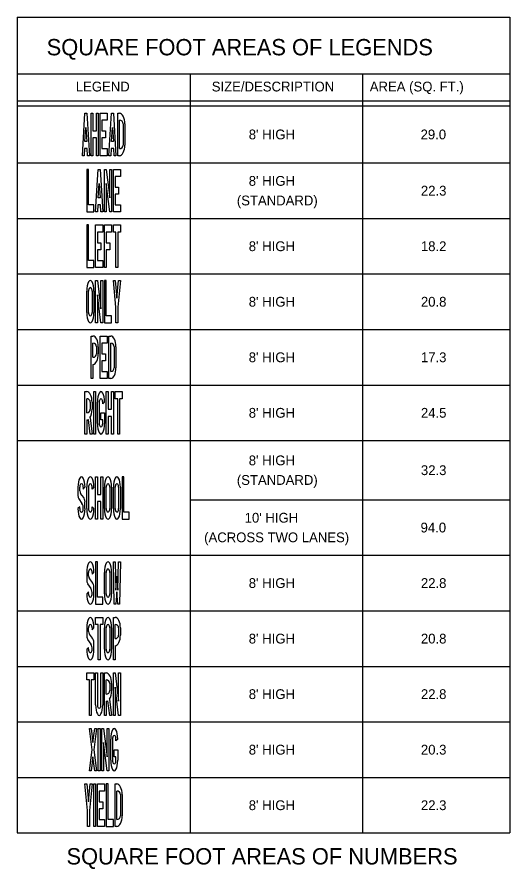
# Model space of a CAD drawing. Extents: x 9999.9 to 10007, y 10023.6 to 10033.8.
# Drawn here: x 10003.69 to 10006.71, y 10028.63 to 10033.85 of the extents above; entities that cross this region are included whole.
import ezdxf

# ---------------------------------------------------------------- set-up
doc = ezdxf.new("R2010")
doc.units = 0
doc.layers.add('DETL-LINE', color=7, linetype='Continuous')
doc.layers.add('DETL-NOTE', color=7, linetype='Continuous')

msp = doc.modelspace()

# ---------------------------------------------------------------- linework, layer by layer
at = {"layer": 'DETL-LINE'}
for points in [[(10004.1029, 10032.9967), (10004.0921, 10032.9967), (10004.1083, 10033.2568), (10004.1192, 10033.2568), (10004.1354, 10032.9967), (10004.1246, 10032.9967), (10004.1219, 10033.0401), (10004.1056, 10033.0401), (10004.1029, 10032.9967)], [(10004.2654, 10032.9967), (10004.2546, 10032.9967), (10004.2709, 10033.2568), (10004.2817, 10033.2568), (10004.2979, 10032.9967), (10004.2871, 10032.9967), (10004.2844, 10033.0401), (10004.2681, 10033.0401), (10004.2654, 10032.9967)], [(10004.3196, 10032.9967), (10004.3088, 10032.9967), (10004.3088, 10033.2568), (10004.3196, 10033.2568)], [(10004.3196, 10033.0401), (10004.3196, 10033.2134)], [(10004.3413, 10033.1917), (10004.3413, 10033.0617)], [(10004.3521, 10033.1917), (10004.3521, 10033.0617)], [(10004.1192, 10033.0834), (10004.1083, 10033.0834), (10004.1138, 10033.1701), (10004.1192, 10033.0834)], [(10004.2817, 10033.0834), (10004.2709, 10033.0834), (10004.2763, 10033.1701), (10004.2817, 10033.0834)], [(10004.1842, 10032.6524), (10004.1734, 10032.6524), (10004.1896, 10032.9124), (10004.2004, 10032.9124), (10004.2167, 10032.6524), (10004.2059, 10032.6524), (10004.2031, 10032.6957), (10004.1869, 10032.6957), (10004.1842, 10032.6524)], [(10004.2004, 10032.7391), (10004.1896, 10032.7391), (10004.195, 10032.8257), (10004.2004, 10032.7391)], [(10004.1192, 10032.0374), (10004.1192, 10032.1674)], [(10004.13, 10032.0374), (10004.13, 10032.1674)], [(10004.1517, 10032.1674), (10004.1517, 10032.0374)], [(10004.1625, 10032.1674), (10004.1625, 10032.0374)], [(10004.1571, 10031.7191), (10004.1571, 10031.6324), (10004.1463, 10031.6324), (10004.1463, 10031.8924), (10004.1571, 10031.8924)], [(10004.2654, 10031.6324), (10004.2546, 10031.6324), (10004.2546, 10031.8924), (10004.2654, 10031.8924)], [(10004.1571, 10031.7624), (10004.1571, 10031.8491)], [(10004.1788, 10031.8274), (10004.1788, 10031.7841)], [(10004.1896, 10031.8274), (10004.1896, 10031.7841)], [(10004.2654, 10031.6757), (10004.2654, 10031.8491)], [(10004.2871, 10031.8274), (10004.2871, 10031.6974)], [(10004.2979, 10031.8274), (10004.2979, 10031.6974)], [(10004.1192, 10031.3791), (10004.1192, 10031.2924), (10004.1083, 10031.2924), (10004.1083, 10031.5524), (10004.1192, 10031.5524)], [(10004.1192, 10031.4224), (10004.1192, 10031.5091)], [(10004.1409, 10031.4874), (10004.1409, 10031.4441)], [(10004.1517, 10031.4874), (10004.1517, 10031.4441)], [(10004.1842, 10031.3574), (10004.1842, 10031.4874)], [(10004.195, 10031.4874), (10004.195, 10031.3574)], [(10004.2275, 10031.4874), (10004.2167, 10031.4766)], [(10004.2167, 10031.4766), (10004.2167, 10031.4874)], [(10004.2167, 10031.3574), (10004.2167, 10031.3791), (10004.2059, 10031.3791), (10004.2059, 10031.4224), (10004.2275, 10031.4224), (10004.2275, 10031.3574)], [(10004.1389, 10031.3923), (10004.1517, 10031.2924), (10004.1409, 10031.2924), (10004.1293, 10031.3823)], [(10004.065, 10030.9663), (10004.065, 10030.9138)], [(10004.0758, 10030.9446), (10004.0758, 10030.9663)], [(10004.0975, 10030.9663), (10004.0975, 10030.9554), (10004.1083, 10030.9663)], [(10004.1192, 10030.8362), (10004.1192, 10030.9663)], [(10004.13, 10030.9663), (10004.13, 10030.8362)], [(10004.1625, 10030.9663), (10004.1517, 10030.9554)], [(10004.1517, 10030.9554), (10004.1517, 10030.9663)], [(10004.2275, 10030.8362), (10004.2275, 10030.9663)], [(10004.2384, 10030.8362), (10004.2384, 10030.9663)], [(10004.26, 10030.9663), (10004.26, 10030.8362)], [(10004.2709, 10030.9663), (10004.2709, 10030.8362)], [(10004.2817, 10030.8362), (10004.2817, 10030.9663)], [(10004.2925, 10030.8362), (10004.2925, 10030.9663)], [(10004.3142, 10030.9663), (10004.3142, 10030.8362)], [(10004.325, 10030.9663), (10004.325, 10030.8362)], [(10004.0704, 10030.8958), (10004.0898, 10030.8682)], [(10004.1002, 10030.904), (10004.0815, 10030.9289)], [(10004.0758, 10030.8362), (10004.0758, 10030.8471), (10004.065, 10030.8362)], [(10004.1083, 10030.8362), (10004.1083, 10030.8769)], [(10004.1517, 10030.8362), (10004.1517, 10030.8471), (10004.1625, 10030.8362)], [(10004.1192, 10030.4451), (10004.1192, 10030.3927)], [(10004.13, 10030.4234), (10004.13, 10030.4451)], [(10004.1517, 10030.4451), (10004.1517, 10030.4343), (10004.1625, 10030.4451)], [(10004.2275, 10030.3151), (10004.2275, 10030.4451)], [(10004.2384, 10030.3151), (10004.2384, 10030.4451)], [(10004.26, 10030.4451), (10004.26, 10030.3151)], [(10004.2709, 10030.4451), (10004.2709, 10030.3151)], [(10004.1246, 10030.3747), (10004.144, 10030.347)], [(10004.1544, 10030.3828), (10004.1357, 10030.4077)], [(10004.13, 10030.3151), (10004.13, 10030.3259), (10004.1192, 10030.3151)], [(10004.1625, 10030.3151), (10004.1625, 10030.3557)], [(10004.2925, 10029.9968), (10004.2925, 10029.9101), (10004.2817, 10029.9101), (10004.2817, 10030.1701), (10004.2925, 10030.1701)], [(10004.1192, 10030.1051), (10004.1192, 10030.0527)], [(10004.13, 10030.0834), (10004.13, 10030.1051)], [(10004.1517, 10030.1051), (10004.1517, 10030.0943), (10004.1625, 10030.1051)], [(10004.2275, 10029.9751), (10004.2275, 10030.1051)], [(10004.2384, 10029.9751), (10004.2384, 10030.1051)], [(10004.26, 10030.1051), (10004.26, 10029.9751)], [(10004.2709, 10030.1051), (10004.2709, 10029.9751)], [(10004.2925, 10030.0401), (10004.2925, 10030.1268)], [(10004.3142, 10030.1051), (10004.3142, 10030.0618)], [(10004.325, 10030.1051), (10004.325, 10030.0618)], [(10004.1544, 10030.0428), (10004.1357, 10030.0677)], [(10004.1246, 10030.0347), (10004.144, 10030.007)], [(10004.1625, 10029.9751), (10004.1625, 10030.0157)], [(10004.13, 10029.9751), (10004.13, 10029.9859), (10004.1192, 10029.9751)], [(10004.1734, 10029.6351), (10004.1734, 10029.8301), (10004.1842, 10029.8301), (10004.1842, 10029.6351)], [(10004.2059, 10029.6351), (10004.2059, 10029.8301), (10004.2167, 10029.8301)], [(10004.2167, 10029.8301), (10004.2167, 10029.6351)], [(10004.2384, 10029.6568), (10004.2384, 10029.5701), (10004.2275, 10029.5701), (10004.2275, 10029.8301), (10004.2384, 10029.8301)], [(10004.2384, 10029.7001), (10004.2384, 10029.7868)], [(10004.26, 10029.7651), (10004.26, 10029.7218)], [(10004.2709, 10029.7651), (10004.2709, 10029.7218)], [(10004.258, 10029.67), (10004.2709, 10029.5701), (10004.26, 10029.5701), (10004.2485, 10029.66)], [(10004.2654, 10029.2951), (10004.2654, 10029.4251)], [(10004.2763, 10029.4251), (10004.2763, 10029.2951)], [(10004.3088, 10029.4251), (10004.2979, 10029.4143)], [(10004.2979, 10029.4143), (10004.2979, 10029.4251)], [(10004.2979, 10029.2951), (10004.2979, 10029.3168), (10004.2871, 10029.3168), (10004.2871, 10029.3601), (10004.3088, 10029.3601), (10004.3088, 10029.2951)], [(10004.3034, 10028.8901), (10004.2925, 10028.8901), (10004.2925, 10029.1501), (10004.3034, 10029.1501)], [(10004.3034, 10028.9334), (10004.3034, 10029.1068)], [(10004.325, 10029.0851), (10004.325, 10028.9551)], [(10004.3359, 10029.0851), (10004.3359, 10028.9551)]]:
    msp.add_lwpolyline(points, dxfattribs=at)
for points in [[(10004.1571, 10032.9967), (10004.1463, 10032.9967), (10004.1463, 10033.2568), (10004.1571, 10033.2568), (10004.1571, 10033.1484), (10004.1788, 10033.1484), (10004.1788, 10033.2568), (10004.1896, 10033.2568), (10004.1896, 10032.9967), (10004.1788, 10032.9967), (10004.1788, 10033.1051), (10004.1571, 10033.1051)], [(10004.2004, 10032.9967), (10004.2004, 10033.2568), (10004.2438, 10033.2568), (10004.2438, 10033.2134), (10004.2113, 10033.2134), (10004.2113, 10033.1484), (10004.2329, 10033.1484), (10004.2329, 10033.1051), (10004.2113, 10033.1051), (10004.2113, 10033.0401), (10004.2438, 10033.0401), (10004.2438, 10032.9967)], [(10004.1625, 10032.6524), (10004.1625, 10032.6957), (10004.13, 10032.6957), (10004.13, 10032.9124), (10004.1192, 10032.9124), (10004.1192, 10032.6524)], [(10004.2384, 10032.6524), (10004.2275, 10032.6524), (10004.2275, 10032.9124), (10004.2384, 10032.9124), (10004.26, 10032.7391), (10004.26, 10032.9124), (10004.2709, 10032.9124), (10004.2709, 10032.6524), (10004.26, 10032.6524), (10004.2384, 10032.8257)], [(10004.2817, 10032.6524), (10004.2817, 10032.9124), (10004.325, 10032.9124), (10004.325, 10032.8691), (10004.2925, 10032.8691), (10004.2925, 10032.8041), (10004.3142, 10032.8041), (10004.3142, 10032.7607), (10004.2925, 10032.7607), (10004.2925, 10032.6957), (10004.325, 10032.6957), (10004.325, 10032.6524)], [(10004.1625, 10032.3124), (10004.1625, 10032.3557), (10004.13, 10032.3557), (10004.13, 10032.5724), (10004.1192, 10032.5724), (10004.1192, 10032.3124)], [(10004.1734, 10032.3124), (10004.1734, 10032.5724), (10004.2167, 10032.5724), (10004.2167, 10032.5291), (10004.1842, 10032.5291), (10004.1842, 10032.4641), (10004.2059, 10032.4641), (10004.2059, 10032.4207), (10004.1842, 10032.4207), (10004.1842, 10032.3557), (10004.2167, 10032.3557), (10004.2167, 10032.3124)], [(10004.2275, 10032.3124), (10004.2275, 10032.5724), (10004.2709, 10032.5724), (10004.2709, 10032.5291), (10004.2384, 10032.5291), (10004.2384, 10032.4641), (10004.26, 10032.4641), (10004.26, 10032.4207), (10004.2384, 10032.4207), (10004.2384, 10032.3124)], [(10004.2979, 10032.3124), (10004.2979, 10032.5291), (10004.2817, 10032.5291), (10004.2817, 10032.5724), (10004.325, 10032.5724), (10004.325, 10032.5291), (10004.3088, 10032.5291), (10004.3088, 10032.3124)], [(10004.1842, 10031.9724), (10004.1734, 10031.9724), (10004.1734, 10032.2324), (10004.1842, 10032.2324), (10004.2059, 10032.0591), (10004.2059, 10032.2324), (10004.2167, 10032.2324), (10004.2167, 10031.9724), (10004.2059, 10031.9724), (10004.1842, 10032.1457)], [(10004.2709, 10031.9724), (10004.2709, 10032.0157), (10004.2384, 10032.0157), (10004.2384, 10032.2324), (10004.2275, 10032.2324), (10004.2275, 10031.9724)], [(10004.2979, 10031.9724), (10004.2979, 10032.0699), (10004.2817, 10032.2324), (10004.2925, 10032.2324), (10004.3034, 10032.1241), (10004.3142, 10032.2324), (10004.325, 10032.2324), (10004.3088, 10032.0699), (10004.3088, 10031.9724)], [(10004.2004, 10031.6324), (10004.2004, 10031.8924), (10004.2438, 10031.8924), (10004.2438, 10031.8491), (10004.2113, 10031.8491), (10004.2113, 10031.7841), (10004.2329, 10031.7841), (10004.2329, 10031.7407), (10004.2113, 10031.7407), (10004.2113, 10031.6757), (10004.2438, 10031.6757), (10004.2438, 10031.6324)], [(10004.1625, 10031.2924), (10004.1625, 10031.5524), (10004.1734, 10031.5524), (10004.1734, 10031.2924)], [(10004.2492, 10031.2924), (10004.2384, 10031.2924), (10004.2384, 10031.5524), (10004.2492, 10031.5524), (10004.2492, 10031.4441), (10004.2709, 10031.4441), (10004.2709, 10031.5524), (10004.2817, 10031.5524), (10004.2817, 10031.2924), (10004.2709, 10031.2924), (10004.2709, 10031.4007), (10004.2492, 10031.4007)], [(10004.3088, 10031.2924), (10004.3088, 10031.5091), (10004.2925, 10031.5091), (10004.2925, 10031.5524), (10004.3359, 10031.5524), (10004.3359, 10031.5091), (10004.3196, 10031.5091), (10004.3196, 10031.2924)], [(10004.1842, 10030.7712), (10004.1734, 10030.7712), (10004.1734, 10031.0313), (10004.1842, 10031.0313), (10004.1842, 10030.9229), (10004.2059, 10030.9229), (10004.2059, 10031.0313), (10004.2167, 10031.0313), (10004.2167, 10030.7712), (10004.2059, 10030.7712), (10004.2059, 10030.8796), (10004.1842, 10030.8796)], [(10004.3792, 10030.7712), (10004.3792, 10030.8146), (10004.3467, 10030.8146), (10004.3467, 10031.0313), (10004.3359, 10031.0313), (10004.3359, 10030.7712)], [(10004.2167, 10030.2501), (10004.2167, 10030.2934), (10004.1842, 10030.2934), (10004.1842, 10030.5101), (10004.1734, 10030.5101), (10004.1734, 10030.2501)], [(10004.2979, 10030.2501), (10004.2871, 10030.2501), (10004.2817, 10030.5101), (10004.2925, 10030.5101), (10004.2979, 10030.3368), (10004.3034, 10030.4234), (10004.3088, 10030.3368), (10004.3142, 10030.5101), (10004.325, 10030.5101), (10004.3196, 10030.2501), (10004.3088, 10030.2501), (10004.3034, 10030.3259)], [(10004.1896, 10029.9101), (10004.1896, 10030.1268), (10004.1734, 10030.1268), (10004.1734, 10030.1701), (10004.2167, 10030.1701), (10004.2167, 10030.1268), (10004.2004, 10030.1268), (10004.2004, 10029.9101)], [(10004.1354, 10029.5701), (10004.1354, 10029.7868), (10004.1192, 10029.7868), (10004.1192, 10029.8301), (10004.1625, 10029.8301), (10004.1625, 10029.7868), (10004.1463, 10029.7868), (10004.1463, 10029.5701)], [(10004.2925, 10029.5701), (10004.2817, 10029.5701), (10004.2817, 10029.8301), (10004.2925, 10029.8301), (10004.3142, 10029.6568), (10004.3142, 10029.8301), (10004.325, 10029.8301), (10004.325, 10029.5701), (10004.3142, 10029.5701), (10004.2925, 10029.7434)], [(10004.1463, 10029.2301), (10004.1354, 10029.2301), (10004.1517, 10029.3601), (10004.1354, 10029.4901), (10004.1463, 10029.4901), (10004.1571, 10029.4034), (10004.1679, 10029.4901), (10004.1788, 10029.4901), (10004.1625, 10029.3601), (10004.1788, 10029.2301), (10004.1679, 10029.2301), (10004.1571, 10029.3168)], [(10004.1896, 10029.2301), (10004.1896, 10029.4901), (10004.2004, 10029.4901), (10004.2004, 10029.2301)], [(10004.2221, 10029.2301), (10004.2113, 10029.2301), (10004.2113, 10029.4901), (10004.2221, 10029.4901), (10004.2438, 10029.3168), (10004.2438, 10029.4901), (10004.2546, 10029.4901), (10004.2546, 10029.2301), (10004.2438, 10029.2301), (10004.2221, 10029.4034)], [(10004.1246, 10028.8901), (10004.1246, 10028.9876), (10004.1083, 10029.1501), (10004.1192, 10029.1501), (10004.13, 10029.0418), (10004.1409, 10029.1501), (10004.1517, 10029.1501), (10004.1354, 10028.9876), (10004.1354, 10028.8901)], [(10004.1625, 10028.8901), (10004.1625, 10029.1501), (10004.1734, 10029.1501), (10004.1734, 10028.8901)], [(10004.1842, 10028.8901), (10004.1842, 10029.1501), (10004.2275, 10029.1501), (10004.2275, 10029.1068), (10004.195, 10029.1068), (10004.195, 10029.0418), (10004.2167, 10029.0418), (10004.2167, 10028.9984), (10004.195, 10028.9984), (10004.195, 10028.9334), (10004.2275, 10028.9334), (10004.2275, 10028.8901)], [(10004.2817, 10028.8901), (10004.2817, 10028.9334), (10004.2492, 10028.9334), (10004.2492, 10029.1501), (10004.2384, 10029.1501), (10004.2384, 10028.8901)]]:
    msp.add_lwpolyline(points, close=True, dxfattribs=at)
for centre, radius, start, end in [((10004.3196, 10033.1917), 0.0217, 0, 90.0002), ((10004.3196, 10033.0617), 0.0217, 269.9998, 0), ((10004.1571, 10031.8274), 0.0217, 0, 90.0002), ((10004.2654, 10031.8274), 0.0217, 0, 90.0002), ((10004.1571, 10031.7841), 0.0217, 269.9998, 0), ((10004.2654, 10031.6974), 0.0217, 269.9998, 0), ((10004.1192, 10031.4874), 0.0217, 0, 90.0002), ((10004.1192, 10031.4441), 0.0217, 269.9998, 0), ((10004.111, 10030.9484), 0.0354, 186.2399, 213.5815), ((10004.1127, 10030.9184), 0.0479, 185.4378, 208.0582), ((10004.0634, 10030.8781), 0.045, 358.1731, 39.5636), ((10004.0432, 10030.8399), 0.0544, 355.4, 31.2385), ((10004.1652, 10030.4273), 0.0354, 186.2399, 213.5815), ((10004.1669, 10030.3972), 0.0479, 185.4378, 208.0582), ((10004.1176, 10030.357), 0.045, 358.1731, 39.5636), ((10004.0974, 10030.3188), 0.0544, 355.4, 31.2385), ((10004.2925, 10030.1051), 0.0217, 0, 90.0002), ((10004.1669, 10030.0572), 0.0479, 185.4378, 208.0582), ((10004.1652, 10030.0873), 0.0354, 186.2399, 213.5815), ((10004.2925, 10030.0618), 0.0217, 269.9998, 0), ((10004.0974, 10029.9788), 0.0544, 355.4, 31.2385), ((10004.1176, 10030.017), 0.045, 358.1731, 39.5636), ((10004.2384, 10029.7651), 0.0217, 0, 90.0002), ((10004.2384, 10029.7218), 0.0217, 269.9998, 0), ((10004.3034, 10029.0851), 0.0217, 0, 90.0002), ((10004.3034, 10028.9551), 0.0217, 269.9998, 0)]:
    msp.add_arc(centre, radius, start, end, dxfattribs=at)
for centre, major_axis, ratio, start_param, end_param in [((10004.3196, 10033.1917), (0, 0.065), 0.5, 4.712389, 6.283189), ((10004.3196, 10033.0617), (0, 0.065), 0.5, 3.141589, 4.712389), ((10004.1409, 10032.1674), (0, 0.065), 0.333333, 4.712389, 7.853989), ((10004.1409, 10032.1674), (0, 0.0217), 0.5, 4.712389, 7.853989), ((10004.1409, 10032.0374), (0, 0.065), 0.333333, 1.570789, 4.712389), ((10004.1409, 10032.0374), (0, 0.0217), 0.5, 1.570789, 4.712389), ((10004.1571, 10031.8274), (0, 0.065), 0.5, 4.712389, 6.283189), ((10004.2654, 10031.8274), (0, 0.065), 0.5, 4.712389, 6.283189), ((10004.1571, 10031.7841), (0, 0.065), 0.5, 3.141589, 4.712389), ((10004.2654, 10031.6974), (0, 0.065), 0.5, 3.141589, 4.712389), ((10004.1192, 10031.4874), (0, 0.065), 0.5, 4.712389, 6.283189), ((10004.2059, 10031.4874), (0, 0.065), 0.333333, 4.712389, 7.853989), ((10004.2059, 10031.4874), (0, 0.0217), 0.5, 4.712389, 7.853989), ((10004.1192, 10031.4441), (0, 0.065), 0.5, 3.792269, 4.712389), ((10004.1192, 10031.4441), (0, 0.065), 0.5, 3.141594, 3.458884), ((10004.1192, 10031.4441), (0, 0.065), 0.5, 3.141594, 3.458884), ((10004.2059, 10031.3574), (0, 0.065), 0.333333, 1.570796, 4.712389), ((10004.2059, 10031.3574), (0, 0.0217), 0.5, 1.570796, 4.712389), ((10004.0867, 10030.9663), (0, 0.065), 0.333333, 4.712389, 7.853982), ((10004.1409, 10030.9663), (0, 0.065), 0.333333, 4.712389, 7.853989), ((10004.1409, 10030.9663), (0, 0.0217), 0.5, 4.712389, 7.853989), ((10004.2492, 10030.9663), (0, 0.065), 0.333333, 4.712389, 7.853989), ((10004.2492, 10030.9663), (0, 0.0217), 0.5, 4.712389, 7.853989), ((10004.3034, 10030.9663), (0, 0.065), 0.333333, 4.712389, 7.853989), ((10004.3034, 10030.9663), (0, 0.0217), 0.5, 4.712389, 7.853989), ((10004.0867, 10030.9663), (0, 0.0217), 0.5, 4.712389, 7.853982), ((10004.0867, 10030.8362), (0, 0.065), 0.333333, 1.570796, 4.712389), ((10004.0867, 10030.8362), (0, 0.0217), 0.5, 1.570796, 4.712389), ((10004.1409, 10030.8362), (0, 0.065), 0.333333, 1.570796, 4.712389), ((10004.1409, 10030.8362), (0, 0.0217), 0.5, 1.570796, 4.712389), ((10004.2492, 10030.8362), (0, 0.065), 0.333333, 1.570789, 4.712389), ((10004.2492, 10030.8362), (0, 0.0217), 0.5, 1.570789, 4.712389), ((10004.3034, 10030.8362), (0, 0.065), 0.333333, 1.570789, 4.712389), ((10004.3034, 10030.8362), (0, 0.0217), 0.5, 1.570789, 4.712389), ((10004.1409, 10030.4451), (0, 0.065), 0.333333, 4.712389, 7.853982), ((10004.2492, 10030.4451), (0, 0.065), 0.333333, 4.712389, 7.853989), ((10004.2492, 10030.4451), (0, 0.0217), 0.5, 4.712389, 7.853989), ((10004.1409, 10030.4451), (0, 0.0217), 0.5, 4.712389, 7.853982), ((10004.1409, 10030.3151), (0, 0.065), 0.333333, 1.570796, 4.712389), ((10004.1409, 10030.3151), (0, 0.0217), 0.5, 1.570796, 4.712389), ((10004.2492, 10030.3151), (0, 0.065), 0.333333, 1.570789, 4.712389), ((10004.2492, 10030.3151), (0, 0.0217), 0.5, 1.570789, 4.712389), ((10004.1409, 10030.1051), (0, 0.065), 0.333333, 4.712389, 7.853982), ((10004.2492, 10030.1051), (0, 0.065), 0.333333, 4.712389, 7.853989), ((10004.2925, 10030.1051), (0, 0.065), 0.5, 4.712389, 6.283189), ((10004.1409, 10030.1051), (0, 0.0217), 0.5, 4.712389, 7.853982), ((10004.2492, 10030.1051), (0, 0.0217), 0.5, 4.712389, 7.853989), ((10004.2925, 10030.0618), (0, 0.065), 0.5, 3.141589, 4.712389), ((10004.1409, 10029.9751), (0, 0.065), 0.333333, 1.570796, 4.712389), ((10004.1409, 10029.9751), (0, 0.0217), 0.5, 1.570796, 4.712389), ((10004.2492, 10029.9751), (0, 0.065), 0.333333, 1.570789, 4.712389), ((10004.2492, 10029.9751), (0, 0.0217), 0.5, 1.570789, 4.712389), ((10004.2384, 10029.7651), (0, 0.065), 0.5, 4.712389, 6.283189), ((10004.2384, 10029.7218), (0, 0.065), 0.5, 3.792269, 4.712389), ((10004.195, 10029.6351), (0, 0.065), 0.333333, 1.570789, 4.712389), ((10004.195, 10029.6351), (0, 0.0217), 0.5, 1.570796, 4.712389), ((10004.2384, 10029.7218), (0, 0.065), 0.5, 3.141594, 3.458884), ((10004.2384, 10029.7218), (0, 0.065), 0.5, 3.141594, 3.458884), ((10004.2871, 10029.4251), (0, 0.065), 0.333333, 4.712389, 7.853989), ((10004.2871, 10029.4251), (0, 0.0217), 0.5, 4.712389, 7.853989), ((10004.2871, 10029.2951), (0, 0.065), 0.333333, 1.570796, 4.712389), ((10004.2871, 10029.2951), (0, 0.0217), 0.5, 1.570796, 4.712389), ((10004.3034, 10029.0851), (0, 0.065), 0.5, 4.712389, 6.283189), ((10004.3034, 10028.9551), (0, 0.065), 0.5, 3.141589, 4.712389)]:
    msp.add_ellipse(centre, major_axis=major_axis, ratio=ratio, start_param=start_param, end_param=end_param, dxfattribs=at)
at = {"layer": 'DETL-NOTE'}
for p, q in [((10003.6926, 10033.8456), (10003.6926, 10028.8501)), ((10003.6926, 10033.8456), (10006.708, 10033.8456)), ((10006.708, 10033.8456), (10006.708, 10028.9569)), ((10003.6926, 10033.4982), (10006.708, 10033.4982)), ((10004.7516, 10033.4982), (10004.7516, 10028.9569)), ((10005.8062, 10033.4982), (10005.8062, 10028.9569)), ((10003.6926, 10033.3323), (10006.708, 10033.3323)), ((10003.6926, 10033.3011), (10006.708, 10033.3011)), ((10003.6926, 10032.9524), (10006.708, 10032.9524)), ((10003.6926, 10032.6124), (10006.708, 10032.6124)), ((10003.6926, 10032.2724), (10006.708, 10032.2724)), ((10003.6926, 10031.9324), (10006.708, 10031.9324)), ((10003.6926, 10031.5924), (10006.708, 10031.5924)), ((10003.6926, 10031.2524), (10006.708, 10031.2524)), ((10004.7516, 10030.8901), (10006.708, 10030.8901)), ((10003.6926, 10030.5501), (10006.708, 10030.5501)), ((10003.6926, 10030.2101), (10006.708, 10030.2101)), ((10003.6926, 10029.8701), (10006.708, 10029.8701)), ((10003.6926, 10029.5301), (10006.708, 10029.5301)), ((10003.6926, 10029.1901), (10006.708, 10029.1901)), ((10004.7516, 10029.2124), (10004.7516, 10028.8501)), ((10005.8062, 10029.2124), (10005.8062, 10028.8501)), ((10006.708, 10029.2124), (10006.708, 10028.8501)), ((10003.6926, 10028.8501), (10006.708, 10028.8501))]:
    msp.add_line(p, q, dxfattribs=at)

# ---------------------------------------------------------------- texts
for s, height, p in [('SQUARE FOOT AREAS OF LEGENDS', 0.1, (10003.8738, 10033.6111)), ('LEGEND', 0.06, (10004.052, 10033.3899)), ('SIZE/DESCRIPTION', 0.06, (10004.8839, 10033.3899)), ('AREA (SQ. FT.)', 0.06, (10005.8504, 10033.3899)), ("8' HIGH", 0.06, (10005.1101, 10033.0967)), ('29.0', 0.06, (10006.1613, 10033.0967)), ("8' HIGH", 0.06, (10005.1101, 10032.8124)), ('22.3', 0.06, (10006.1633, 10032.7524)), ('(STANDARD)', 0.06, (10005.0372, 10032.6924)), ("8' HIGH", 0.06, (10005.1101, 10032.4124)), ('18.2', 0.06, (10006.1633, 10032.4124)), ("8' HIGH", 0.06, (10005.1101, 10032.0724)), ('20.8', 0.06, (10006.1633, 10032.0724)), ("8' HIGH", 0.06, (10005.1101, 10031.7324)), ('17.3', 0.06, (10006.1633, 10031.7324)), ("8' HIGH", 0.06, (10005.1101, 10031.3924)), ('24.5', 0.06, (10006.1633, 10031.3924)), ("8' HIGH", 0.06, (10005.1101, 10031.1012)), ('32.3', 0.06, (10006.1633, 10031.0412)), ('(STANDARD)', 0.06, (10005.0372, 10030.9812)), ("10' HIGH", 0.06, (10005.0851, 10030.7501)), ('94.0', 0.06, (10006.1613, 10030.6901)), ('(ACROSS TWO LANES)', 0.06, (10004.8372, 10030.6301)), ("8' HIGH", 0.06, (10005.1101, 10030.3501)), ('22.8', 0.06, (10006.1633, 10030.3501)), ("8' HIGH", 0.06, (10005.1101, 10030.0101)), ('20.8', 0.06, (10006.1633, 10030.0101)), ("8' HIGH", 0.06, (10005.1101, 10029.6701)), ('22.8', 0.06, (10006.1633, 10029.6701)), ("8' HIGH", 0.06, (10005.1101, 10029.3301)), ('20.3', 0.06, (10006.1633, 10029.3301)), ("8' HIGH", 0.06, (10005.1101, 10028.9901)), ('22.3', 0.06, (10006.1633, 10028.9901)), ('SQUARE FOOT AREAS OF NUMBERS', 0.1, (10003.9951, 10028.6573))]:
    msp.add_text(s, height=height, dxfattribs=at).set_placement(p)

doc.saveas('drawing.dxf')
